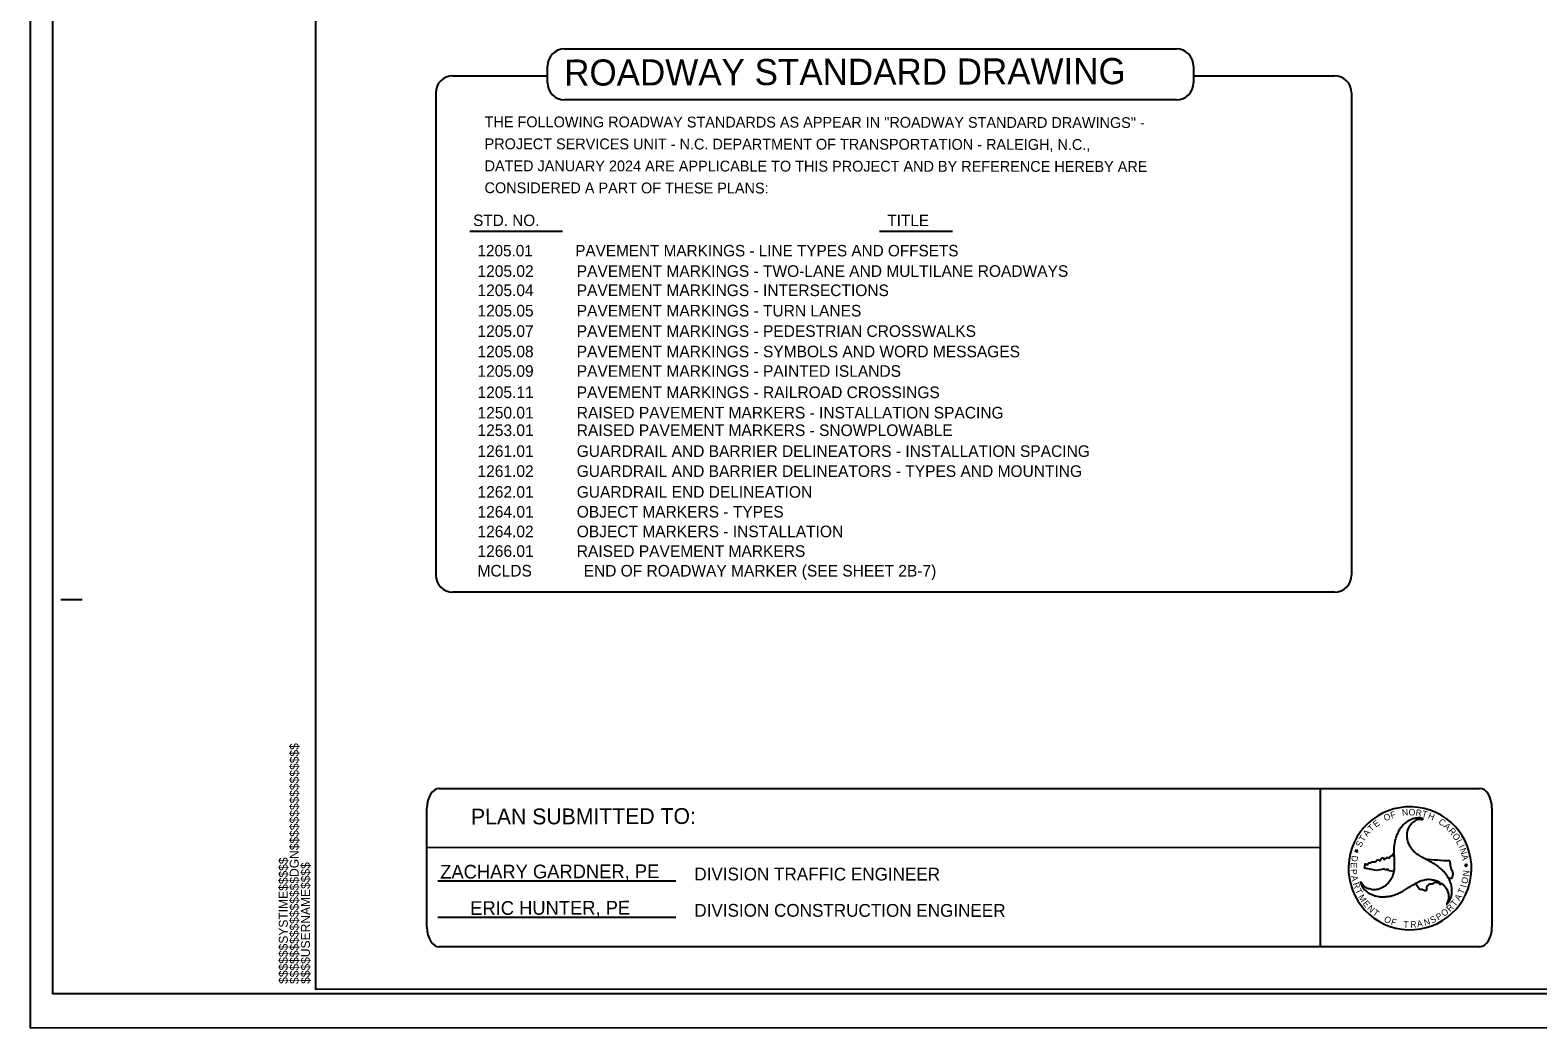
# Model space of a CAD drawing. Extents: x 2088685 to 2091711, y 751320 to 752417.
# Drawn here: x 2089192 to 2090071, y 751321 to 751903 of the extents above; entities that cross this region are included whole.
import ezdxf

# ---------------------------------------------------------------- set-up
doc = ezdxf.new("R2010")
doc.units = 0
for name, color, linetype in [('Default', 7, 'Continuous'), ('Sheet Block Title CELL', 7, 'Continuous'), ('Sheet Plan CELL', 7, 'Continuous'), ('Sheet Plot Border Inside CELL', 7, 'Continuous'), ('Sheet Plot Border Outside CELL', 7, 'Continuous'), ('Sheet Title CELL', 7, 'Continuous')]:
    doc.layers.add(name, color=color, linetype=linetype)

msp = doc.modelspace()

# ---------------------------------------------------------------- linework, layer by layer
at = {"layer": 'Default'}
for p, q in [((2089430.57, 751460.75), (2090037.5, 751460.85)), ((2089944.43, 751460.83), (2089944.46, 751368.49)), ((2089423.39, 751379.93), (2089423.37, 751449.31)), ((2090044.7, 751449.36), (2090044.72, 751380)), ((2089423.36, 751426.39), (2089944.44, 751426.61)), ((2089429.75, 751406.99), (2089568.61, 751406.93)), ((2089429.75, 751385.81), (2089568.61, 751385.74)), ((2090037.52, 751368.5), (2089430.59, 751368.39))]:
    msp.add_line(p, q, dxfattribs=at)
for centre, major_axis, start_param, end_param in [((2089430.57, 751449.31), (0.01, 11.49), 0.000702, 1.571498), ((2090037.5, 751449.36), (0.01, 11.49), 4.713091, 6.283887), ((2089430.59, 751379.94), (-0.01, -11.49), 4.713091, 6.283887), ((2090037.52, 751379.99), (-0.01, -11.49), 0.000702, 1.571498)]:
    msp.add_ellipse(centre, major_axis=major_axis, ratio=0.62659, start_param=start_param, end_param=end_param, dxfattribs=at)
at = {"layer": 'Sheet Block Title CELL'}
msp.add_lwpolyline([(2090858, 752393.6), (2089358.33, 752393.49), (2089358.41, 751343.72), (2090858.08, 751343.83)], close=True, dxfattribs=at)
at = {"layer": 'Sheet Plan CELL'}
for p, q in [((2089204.94, 751341.13), (2089204.94, 751341.13)), ((2089191.96, 751321.13), (2089191.96, 751321.13))]:
    msp.add_line(p, q, dxfattribs=at)
at = {"layer": 'Sheet Plot Border Inside CELL'}
msp.add_line((2089209.8, 751571.08), (2089222.3, 751571.09), dxfattribs=at)
msp.add_lwpolyline([(2090869.93, 752396.91), (2089204.86, 752396.79), (2089204.94, 751341.13), (2090870.01, 751341.25)], close=True, dxfattribs=at)
at = {"layer": 'Sheet Plot Border Outside CELL'}
msp.add_lwpolyline([(2090874.42, 752416.91), (2089191.88, 752416.79), (2089191.96, 751321.13), (2090874.5, 751321.25)], close=True, dxfattribs=at)
at = {"layer": 'Sheet Title CELL'}
for p, q in [((2089428.47, 751866.75), (2089428.47, 751585.4)), ((2089962.82, 751866.75), (2089962.82, 751585.4)), ((2089448.31, 751786.13), (2089502.5, 751786.1)), ((2089687.3, 751786.08), (2089730.02, 751786.06)), ((2090004.73, 751443.12), (2090004.66, 751443.05)), ((2090004.73, 751443.12), (2090004.66, 751443.05)), ((2089965.48, 751424.59), (2089965.73, 751425.16)), ((2089965.73, 751425.16), (2089965.87, 751424.54)), ((2089965.3, 751424.23), (2089964.83, 751424.68)), ((2089964.83, 751424.68), (2089965.48, 751424.59)), ((2089965.03, 751423.64), (2089965.3, 751424.23)), ((2089965.57, 751423.95), (2089965.03, 751423.64)), ((2089966.05, 751423.5), (2089965.57, 751423.95)), ((2089965.87, 751424.54), (2089966.51, 751424.46)), ((2089966.51, 751424.46), (2089965.93, 751424.14)), ((2089965.93, 751424.14), (2089966.05, 751423.5)), ((2089970.27, 751414.23), (2089970.64, 751416.45)), ((2090005.67, 751419.79), (2090005.67, 751419.79)), ((2090029.44, 751416.3), (2090028.81, 751416.38)), ((2090028.81, 751416.38), (2090029.28, 751415.94)), ((2090029.72, 751416.86), (2090029.44, 751416.3)), ((2090029.86, 751416.24), (2090029.72, 751416.86)), ((2089977.27, 751413.03), (2089970.27, 751414.23)), ((2089981.47, 751413.68), (2089977.27, 751413.03)), ((2089987.44, 751412.38), (2089984.51, 751412.8)), ((2090029.28, 751415.94), (2090029.02, 751415.35)), ((2090029.02, 751415.35), (2090029.56, 751415.65)), ((2090029.56, 751415.65), (2090030.03, 751415.21)), ((2090030.49, 751416.18), (2090029.86, 751416.24)), ((2090029.92, 751415.85), (2090030.49, 751416.18)), ((2090030.03, 751415.21), (2090029.92, 751415.85)), ((2090002.71, 751401.58), (2090000.05, 751405.37)), ((2090000.05, 751405.37), (2090000.05, 751405.37))]:
    msp.add_line(p, q, dxfattribs=at)
for points in [[(2089503.69, 751892.41), (2089860.59, 751892.41)], [(2089438.47, 751876.75), (2089493.69, 751876.75)], [(2089493.69, 751872.6), (2089493.69, 751882.41)], [(2089870.59, 751882.41), (2089870.59, 751872.6)], [(2089870.59, 751876.75), (2089952.82, 751876.75)], [(2089860.59, 751862.6), (2089503.69, 751862.6)], [(2089952.82, 751575.4), (2089438.47, 751575.4)]]:
    msp.add_lwpolyline(points, dxfattribs=at)
for centre, radius, start, end in [((2089503.69, 751882.41), 10, 90, 180), ((2089860.59, 751882.41), 10, 0, 90), ((2089438.47, 751866.75), 10, 90, 180), ((2089952.82, 751866.75), 10, 0, 90), ((2089503.69, 751872.6), 10, 180, 270), ((2089860.59, 751872.6), 10, 270, 0), ((2089438.47, 751585.4), 10, 180, 270), ((2089952.82, 751585.4), 10, 270, 0), ((2089996.89, 751414.24), 35.88, 352.42113, 172.42113), ((2089996.89, 751414.24), 35.88, 172.42113, 352.42113), ((2090027.88, 751615.96), 197.41, 258.09962, 258.19922), ((2090027.88, 751615.96), 197.41, 263.53868, 267.74469)]:
    msp.add_arc(centre, radius, start, end, dxfattribs=at)
for points in [[(2090004.66, 751443.05), (2090003.85, 751443.38), (2090001.37, 751443.61), (2089998.76, 751443.14), (2089998.52, 751443.05), (2089997.18, 751442.55), (2089995.72, 751441.74), (2089993.45, 751440.11), (2089991.6, 751437.97), (2089990.85, 751437.05), (2089990.23, 751435.88), (2089989.06, 751433.37), (2089988.29, 751430.9), (2089987.74, 751427.96), (2089987.43, 751425.36), (2089987.51, 751422.65), (2089987.62, 751419.91), (2089987.66, 751417.27), (2089987.66, 751414.54), (2089987.32, 751411.89), (2089987.28, 751411.66), (2089986.43, 751408.9), (2089984.96, 751406.57), (2089983.21, 751404.69), (2089982.21, 751403.85), (2089980.84, 751403.05), (2089980.06, 751402.58), (2089978.26, 751401.95), (2089975.64, 751401.69), (2089973.18, 751402.16), (2089971.05, 751403.02), (2089969.28, 751404.52), (2089967.99, 751406.5)], [(2090018, 751393.03), (2090018.65, 751393.55), (2090020.11, 751395.58), (2090021.01, 751398.08), (2090021.08, 751398.33), (2090021.29, 751399.75), (2090021.32, 751401.43), (2090021.06, 751404.21), (2090020.11, 751406.87), (2090019.71, 751407.99), (2090018.98, 751409.12), (2090017.4, 751411.38), (2090015.65, 751413.28), (2090013.38, 751415.22), (2090011.27, 751416.77), (2090008.88, 751418.09), (2090006.47, 751419.35), (2090004.18, 751420.63), (2090001.78, 751422), (2089999.67, 751423.62), (2089999.51, 751423.78), (2089997.51, 751425.91), (2089996.24, 751428.35), (2089995.47, 751430.79), (2089995.28, 751432.06), (2089995.27, 751433.66), (2089995.22, 751434.59), (2089995.6, 751436.44), (2089996.69, 751438.86), (2089998.31, 751440.74), (2090000.12, 751442.14), (2090002.32, 751442.92), (2090004.66, 751443.05), (2090004.73, 751443.12)], [(2089970.64, 751416.45), (2089970.59, 751416.67), (2089971, 751416.86), (2089971.99, 751416.29), (2089972.58, 751416.67), (2089972.61, 751417.13), (2089973.09, 751417.52), (2089973.79, 751417.29), (2089974.55, 751418.02), (2089975.16, 751418.09), (2089976.41, 751417.92), (2089978.1, 751419.22), (2089978.74, 751419.22), (2089978.84, 751418.81), (2089979.21, 751418.68), (2089980.01, 751419.83), (2089980.2, 751419.98), (2089981.43, 751420.29), (2089981.71, 751420.03), (2089981.72, 751419.47), (2089981.87, 751419.33), (2089982.3, 751419.56), (2089982.9, 751420.15), (2089983.92, 751420.52), (2089985, 751420.24), (2089985.3, 751421.11), (2089986.69, 751421.79), (2089987.02, 751422.28), (2089987.16, 751422.8)], [(2089987.51, 751422.72), (2089987.51, 751422.65), (2089987.62, 751419.91), (2089987.66, 751417.27), (2089987.66, 751414.54), (2089987.43, 751412.38)], [(2090019.48, 751408.42), (2090018.98, 751409.12), (2090017.4, 751411.38), (2090015.65, 751413.28), (2090013.38, 751415.22), (2090011.27, 751416.77), (2090008.88, 751418.09), (2090006.47, 751419.35), (2090005.67, 751419.79)], [(2090020.11, 751418.69), (2090020.31, 751416.15), (2090021.22, 751413.06), (2090021.84, 751411.35), (2090021.64, 751409.98), (2090021.1, 751408.38), (2090019.5, 751408.43)], [(2089967.99, 751406.5), (2089968.14, 751405.63), (2089969.17, 751403.37), (2089970.87, 751401.33), (2089971.06, 751401.19), (2089972.18, 751400.25), (2089973.61, 751399.41), (2089976.17, 751398.24), (2089978.92, 751397.74), (2089980.09, 751397.53), (2089981.48, 751397.59), (2089984.18, 751397.83), (2089986.69, 751398.38), (2089989.53, 751399.38), (2089991.91, 751400.42), (2089994.25, 751401.85), (2089996.55, 751403.32), (2089998.83, 751404.66), (2090001.2, 751406.01), (2090003.65, 751407.07), (2090003.92, 751407.13), (2090006.74, 751407.79), (2090009.45, 751407.67), (2090011.93, 751407.12), (2090013.21, 751406.67), (2090014.54, 751405.85), (2090015.39, 751405.44), (2090016.8, 751404.18), (2090018.32, 751402.05), (2090019.15, 751399.7), (2090019.47, 751397.4), (2090019.06, 751395.12), (2090018, 751393.03)], [(2089984.51, 751412.8), (2089984.3, 751413.38), (2089983.75, 751413.62), (2089982.92, 751413.32), (2089982.34, 751413.43), (2089981.77, 751413.97), (2089981.47, 751413.68)], [(2090000.05, 751405.37), (2090001.2, 751406.01), (2090003.65, 751407.07), (2090003.92, 751407.13), (2090006.74, 751407.79), (2090009.45, 751407.67), (2090011.93, 751407.12), (2090013.21, 751406.67), (2090014.54, 751405.85), (2090015.33, 751405.46)], [(2090015.32, 751405.45), (2090014.89, 751404.84), (2090014.32, 751404.87), (2090013.45, 751405.78), (2090012.22, 751405.7), (2090011.71, 751406.09), (2090011.35, 751406.15), (2090010.33, 751405.18), (2090009.11, 751405.07), (2090006.99, 751403.91), (2090006.49, 751403.14), (2090006.39, 751401.34), (2090005.87, 751401.05), (2090005.31, 751401.21), (2090004.19, 751401.83), (2090002.71, 751401.58)]]:
    msp.add_spline(points, degree=3, dxfattribs=at)

# ---------------------------------------------------------------- texts
at = {"layer": 'Default'}
for s, height, rotation, p in [('ROADWAY STANDARD DRAWING', 15.2572, 0.15565, (2089503.48, 751870.96)), ('THE FOLLOWING ROADWAY STANDARDS AS APPEAR IN "ROADWAY STANDARD DRAWINGS" -', 6.3, 359.93321, (2089457.02, 751846.7)), ('PROJECT SERVICES UNIT - N.C. DEPARTMENT OF TRANSPORTATION - RALEIGH, N.C.,', 6.3, 359.93321, (2089457.01, 751833.88)), ('DATED JANUARY 2024 ARE APPLICABLE TO THIS PROJECT AND BY REFERENCE HEREBY ARE ', 6.3, 359.93321, (2089456.99, 751821.05)), ('CONSIDERED A PART OF THESE PLANS:', 6.3, 359.93321, (2089456.98, 751808.23)), ('STD. NO.', 6.671, 359.97341, (2089450.34, 751789.06)), ('TITLE', 6.671, 359.97341, (2089692, 751789.01)), ('1205.02          PAVEMENT MARKINGS - TWO-LANE AND MULTILANE ROADWAYS', 6.7709, 360, (2089452.88, 751759.39)), ('1205.04          PAVEMENT MARKINGS - INTERSECTIONS', 6.7709, 360, (2089452.88, 751748.16)), ('1205.05          PAVEMENT MARKINGS - TURN LANES', 6.7709, 360, (2089452.88, 751736.26)), ('1205.07          PAVEMENT MARKINGS - PEDESTRIAN CROSSWALKS', 6.7709, 360, (2089452.88, 751724.35)), ('1205.08          PAVEMENT MARKINGS - SYMBOLS AND WORD MESSAGES', 6.7709, 360, (2089452.88, 751712.45)), ('1205.09          PAVEMENT MARKINGS - PAINTED ISLANDS', 6.7709, 360, (2089452.88, 751701.05)), ('1205.11          PAVEMENT MARKINGS - RAILROAD CROSSINGS', 6.7709, 360, (2089452.88, 751688.64)), ('1250.01          RAISED PAVEMENT MARKERS - INSTALLATION SPACING', 6.7709, 360, (2089452.88, 751676.74)), ('1253.01          RAISED PAVEMENT MARKERS - SNOWPLOWABLE', 6.7709, 360, (2089452.88, 751666.5)), ('1261.01          GUARDRAIL AND BARRIER DELINEATORS - INSTALLATION SPACING', 6.7709, 360, (2089452.88, 751654.3)), ('1261.02          GUARDRAIL AND BARRIER DELINEATORS - TYPES AND MOUNTING', 6.7709, 360, (2089452.88, 751642.64)), ('1262.01          GUARDRAIL END DELINEATION', 6.7709, 360, (2089452.88, 751630.5)), ('1264.01          OBJECT MARKERS - TYPES', 6.7709, 360, (2089452.88, 751618.92)), ('1264.02          OBJECT MARKERS - INSTALLATION', 6.7709, 360, (2089452.88, 751607.44)), ('1266.01          RAISED PAVEMENT MARKERS', 6.7709, 360, (2089452.88, 751595.97)), ('MCLDS            END OF ROADWAY MARKER (SEE SHEET 2B-7)', 6.7709, 360, (2089452.88, 751584.5)), ('$$$$$$$$$$$$$$$$DGN$$$$$$$$$$$$$$$$', 5.2488, 90.00421, (2089348.56, 751346.72)), ('PLAN SUBMITTED TO:', 9.2466, 0.15565, (2089449.06, 751439.78)), ('$$$$$$SYSTIME$$$$$', 5.2488, 90.00421, (2089342.21, 751346.82)), ('$$$$USERNAME$$$$', 5.2488, 90.00421, (2089355.11, 751346.77)), ('ZACHARY GARDNER, PE', 8, 0.15565, (2089431.13, 751408.2)), ('DIVISION TRAFFIC ENGINEER', 7.4502, 359.97341, (2089579.38, 751407.17)), ('ERIC HUNTER, PE', 8, 0.15565, (2089448.62, 751387.01)), ('DIVISION CONSTRUCTION ENGINEER', 7.4502, 359.97341, (2089579.37, 751385.99))]:
    msp.add_text(s, height=height, rotation=rotation, dxfattribs=at).set_placement(p)
at = {"layer": 'Sheet Title CELL'}
msp.add_text('1205.01          PAVEMENT MARKINGS - LINE TYPES AND OFFSETS', height=6.6709, dxfattribs=at).set_placement((2089452.88, 751771.34))
for s, height, rotation, p in [('E', 3.72, 36.57807, (2089976.98, 751437.92)), ('O', 3.74, 24.63869, (2089982.49, 751441.6)), ('F', 3.74, 17.49185, (2089986.08, 751443.22)), ('N', 3.73, 5.40491, (2089992.38, 751444.84)), ('O', 3.74, 357.9068, (2089996.01, 751445.16)), ('R', 3.73, 351.29687, (2089999.96, 751445.02)), ('T', 3.74, 344.64724, (2090003.49, 751444.48)), ('H', 3.73, 337.56252, (2090007.01, 751443.49)), ('C', 3.72, 325.22017, (2090013.12, 751440.59)), ('A', 3.75, 50.74892, (2089971.88, 751432.42)), ('T', 3.72, 43.6937, (2089974.33, 751435.41)), ('A', 3.73, 317.72314, (2090016.17, 751438.45)), ('R', 3.73, 311.35919, (2090019.01, 751435.88)), ('O', 3.74, 304.23959, (2090021.36, 751433.19)), ('S', 3.73, 64.17738, (2089968.34, 751426.16)), ('T', 3.74, 57.80123, (2089969.9, 751429.36)), ('L', 3.72, 298.00591, (2090023.6, 751429.9)), ('I', 3.74, 294.01657, (2090025.05, 751427.02)), ('N', 3.73, 288.31647, (2090025.77, 751425.35)), ('E', 3.72, 266.56202, (2089962.39, 751417.71)), ('D', 3.73, 260.27413, (2089963.08, 751421.94)), ('A', 3.73, 280.88449, (2090026.89, 751421.86)), ('P', 3.73, 274.09441, (2089962.22, 751413.65)), ('A', 3.73, 280.68699, (2089962.51, 751409.67)), ('O', 3.72, 77.38125, (2090030.32, 751404.95)), ('N', 3.73, 84.62926, (2090031.26, 751409.36)), ('R', 3.73, 287.75562, (2089963.38, 751405.34)), ('T', 3.73, 294.40616, (2089964.67, 751401.43)), ('M', 3.72, 301.6412, (2089966.48, 751397.59)), ('T', 3.73, 66.59571, (2090027.95, 751398.78)), ('I', 3.74, 72.24562, (2090029.61, 751402.66)), ('E', 3.72, 309.10797, (2089969.03, 751393.59)), ('N', 3.74, 316.07951, (2089971.61, 751390.49)), ('T', 3.73, 322.92151, (2089974.67, 751387.6)), ('O', 3.74, 38.13535, (2090016.77, 751385.81)), ('R', 3.74, 45.32446, (2090020.3, 751388.62)), ('T', 3.72, 51.42425, (2090023.17, 751391.59)), ('A', 3.74, 59.51129, (2090025.75, 751394.94)), ('O', 3.73, 336.2252, (2089981.34, 751383.23)), ('F', 3.73, 343.39043, (2089985.49, 751381.47)), ('T', 3.72, 356.29966, (2089992.93, 751379.76)), ('R', 3.74, 3.25628, (2089997.16, 751379.54)), ('A', 3.72, 10.00941, (2090001.27, 751379.83)), ('N', 3.72, 17.04104, (2090005.6, 751380.66)), ('S', 3.72, 24.25151, (2090009.62, 751381.98)), ('P', 3.73, 31.44336, (2090013.37, 751383.69))]:
    msp.add_text(s, height=height, rotation=rotation, dxfattribs=at).set_placement(p)

doc.saveas('drawing.dxf')
